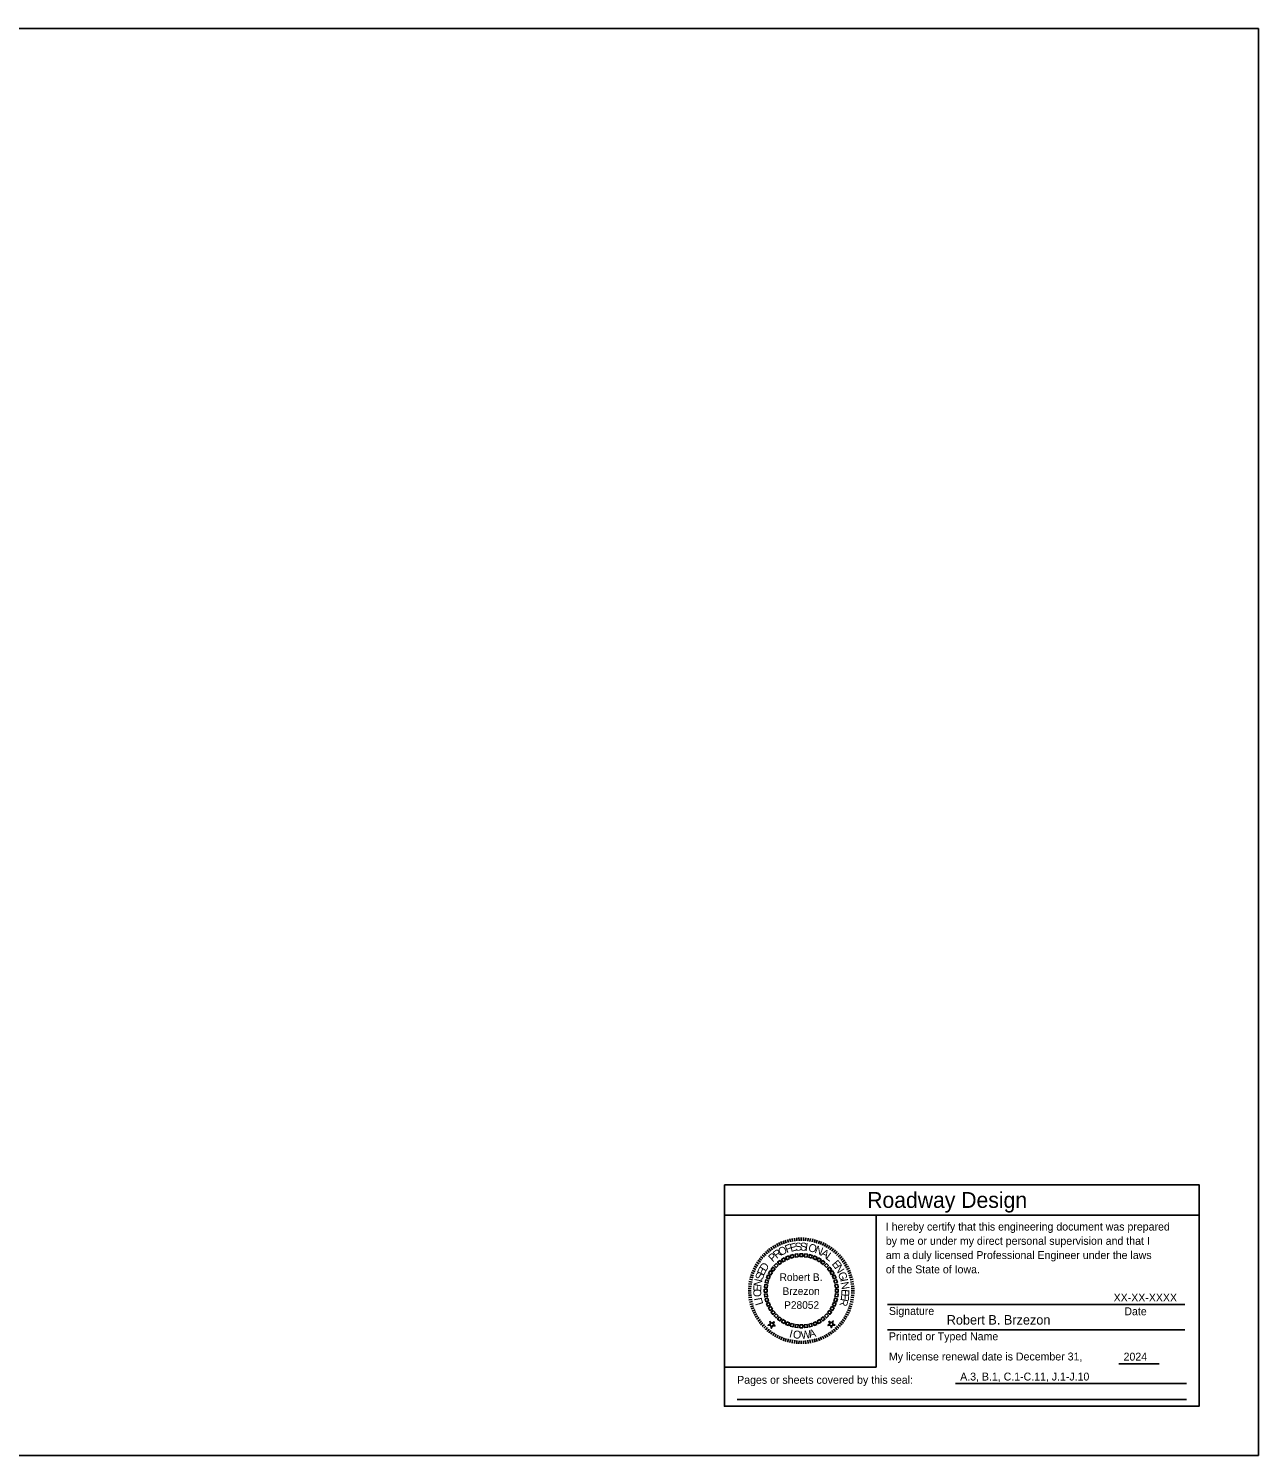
# Model space of a CAD drawing. Extents: x 10133 to 81668, y 7924 to 11018.
# Drawn here: x 11526 to 13268, y 7924 to 9944 of the extents above; entities that cross this region are included whole.
import ezdxf

# ---------------------------------------------------------------- set-up
doc = ezdxf.new("R2010")
doc.units = 0
for name, color, linetype in [('Level 1', 7, 'Continuous'), ('Level 20', 7, 'Continuous'), ('Level 21', 7, 'Continuous'), ('Level 22', 7, 'Continuous'), ('Level 4', 7, 'Continuous'), ('SheetBorder', 7, 'Continuous'), ('SheetText', 7, 'Continuous')]:
    doc.layers.add(name, color=color, linetype=linetype)

msp = doc.modelspace()

# ---------------------------------------------------------------- linework, layer by layer
at = {"layer": 'Level 20'}
msp.add_lwpolyline([(12511.5, 8307.2), (13183.4, 8307.2), (13183.4, 7993.7), (12511.5, 7993.7)], close=True, dxfattribs=at)
at = {"layer": 'Level 21'}
for p, q in [((12511.5, 8264.2), (13183.4, 8264.2)), ((12726.5, 8049.2), (12726.5, 8264.2)), ((12511.5, 8049.2), (12726.5, 8049.2))]:
    msp.add_line(p, q, dxfattribs=at)
msp.add_lwpolyline([(12511.5, 8307.2), (13183.4, 8307.2), (13183.4, 7993.7), (12511.5, 7993.7)], close=True, dxfattribs=at)
at = {"layer": 'Level 22'}
for p, q in [((13163.3, 8137.7), (12742.3, 8137.7)), ((13163.3, 8101.9), (12742.3, 8101.9)), ((13126.9, 8053.9), (13069.7, 8053.9)), ((12838.5, 8025.7), (13165.5, 8025.7)), ((12529.5, 8003.3), (13165.5, 8003.3))]:
    msp.add_line(p, q, dxfattribs=at)
at = {"layer": 'Level 4'}
for p, q in [((12584.9, 8218.5), (12582.7, 8222.4)), ((12587.7, 8220), (12585.6, 8224)), ((12590.4, 8221.3), (12588.5, 8225.4)), ((12593.2, 8222.6), (12591.5, 8226.7)), ((12596.1, 8223.7), (12594.6, 8227.9)), ((12599.1, 8224.7), (12597.7, 8229)), ((12602, 8225.6), (12600.9, 8229.9)), ((12605, 8226.3), (12604, 8230.7)), ((12608, 8226.9), (12607.3, 8231.3)), ((12611.1, 8227.4), (12610.5, 8231.8)), ((12614.2, 8227.7), (12613.8, 8232.2)), ((12617.2, 8227.9), (12617, 8232.4)), ((12620.3, 8228), (12620.3, 8232.5)), ((12623.4, 8227.9), (12623.6, 8232.4)), ((12626.5, 8227.7), (12626.9, 8232.2)), ((12629.6, 8227.4), (12630.2, 8231.8)), ((12632.6, 8226.9), (12633.4, 8231.3)), ((12635.6, 8226.3), (12636.6, 8230.7)), ((12638.6, 8225.6), (12639.8, 8229.9)), ((12641.6, 8224.7), (12643, 8229)), ((12644.5, 8223.7), (12646.1, 8227.9)), ((12647.4, 8222.6), (12649.1, 8226.7)), ((12650.2, 8221.3), (12652.1, 8225.4)), ((12653, 8220), (12655.1, 8224)), ((12655.7, 8218.5), (12658, 8222.4)), ((12564.2, 8200.3), (12560.6, 8203)), ((12566.1, 8202.7), (12562.7, 8205.6)), ((12568.2, 8205), (12564.9, 8208)), ((12570.3, 8207.3), (12567.1, 8210.4)), ((12572.5, 8209.4), (12569.5, 8212.7)), ((12574.8, 8211.4), (12572, 8214.9)), ((12577.2, 8213.4), (12574.5, 8216.9)), ((12579.7, 8215.2), (12577.2, 8218.9)), ((12582.3, 8216.9), (12579.9, 8220.7)), ((12658.4, 8216.9), (12660.8, 8220.7)), ((12660.9, 8215.2), (12663.5, 8218.8)), ((12663.4, 8213.4), (12666.1, 8216.9)), ((12665.8, 8211.4), (12668.7, 8214.9)), ((12668.1, 8209.4), (12671.2, 8212.7)), ((12670.4, 8207.3), (12673.5, 8210.4)), ((12672.5, 8205), (12675.8, 8208)), ((12674.5, 8202.7), (12678, 8205.6)), ((12676.5, 8200.3), (12680, 8203)), ((12553.8, 8181.4), (12549.6, 8182.9)), ((12554.9, 8184.3), (12550.8, 8186)), ((12556.2, 8187.1), (12552.1, 8189)), ((12557.6, 8189.9), (12553.6, 8192)), ((12559, 8192.6), (12555.2, 8194.8)), ((12560.6, 8195.2), (12556.9, 8197.6)), ((12562.4, 8197.8), (12558.7, 8200.4)), ((12678.3, 8197.8), (12682, 8200.4)), ((12680, 8195.2), (12683.8, 8197.6)), ((12681.6, 8192.6), (12685.5, 8194.8)), ((12683.1, 8189.9), (12687.1, 8192)), ((12684.5, 8187.1), (12688.5, 8189)), ((12685.7, 8184.3), (12689.9, 8186)), ((12686.8, 8181.4), (12691, 8182.9)), ((12549.8, 8163.4), (12545.4, 8163.8)), ((12550.2, 8166.4), (12545.7, 8167)), ((12550.6, 8169.5), (12546.2, 8170.3)), ((12551.2, 8172.5), (12546.9, 8173.5)), ((12552, 8175.5), (12547.6, 8176.7)), ((12552.8, 8178.5), (12548.6, 8179.8)), ((12687.8, 8178.5), (12692.1, 8179.8)), ((12688.7, 8175.5), (12693, 8176.7)), ((12689.4, 8172.5), (12693.8, 8173.5)), ((12690, 8169.5), (12694.4, 8170.3)), ((12690.5, 8166.4), (12694.9, 8167)), ((12690.8, 8163.4), (12695.3, 8163.8)), ((12549.6, 8157.2), (12545.1, 8157.2)), ((12549.6, 8160.3), (12545.2, 8160.5)), ((12549.6, 8154.1), (12545.2, 8153.9)), ((12549.8, 8151), (12545.4, 8150.7)), ((12550.2, 8148), (12545.7, 8147.4)), ((12550.6, 8144.9), (12546.2, 8144.1)), ((12551.2, 8141.9), (12546.9, 8140.9)), ((12689.4, 8141.9), (12693.8, 8140.9)), ((12690, 8144.9), (12694.4, 8144.1)), ((12690.5, 8148), (12694.9, 8147.4)), ((12690.8, 8151), (12695.3, 8150.6)), ((12691, 8160.3), (12695.5, 8160.5)), ((12691, 8154.1), (12695.5, 8153.9)), ((12691.1, 8157.2), (12695.6, 8157.2)), ((12552, 8138.9), (12547.6, 8137.7)), ((12552.8, 8135.9), (12548.6, 8134.6)), ((12553.8, 8133), (12549.6, 8131.5)), ((12554.9, 8130.1), (12550.8, 8128.4)), ((12556.2, 8127.3), (12552.1, 8125.4)), ((12557.6, 8124.5), (12553.6, 8122.5)), ((12559, 8121.8), (12555.2, 8119.6)), ((12681.6, 8121.8), (12685.5, 8119.6)), ((12683.1, 8124.5), (12687.1, 8122.5)), ((12684.5, 8127.3), (12688.5, 8125.4)), ((12685.7, 8130.1), (12689.9, 8128.4)), ((12686.8, 8133), (12691, 8131.5)), ((12687.8, 8135.9), (12692.1, 8134.6)), ((12688.7, 8138.9), (12693, 8137.7)), ((12560.6, 8119.2), (12556.9, 8116.8)), ((12562.4, 8116.6), (12558.7, 8114)), ((12564.2, 8114.1), (12560.6, 8111.4)), ((12566.1, 8111.7), (12562.7, 8108.8)), ((12568.2, 8109.4), (12564.8, 8106.4)), ((12570.3, 8107.2), (12567.1, 8104)), ((12572.5, 8105), (12569.5, 8101.7)), ((12574.8, 8103), (12572, 8099.6)), ((12577.2, 8101.1), (12574.5, 8097.5)), ((12663.4, 8101.1), (12666.1, 8097.5)), ((12665.8, 8103), (12668.7, 8099.6)), ((12668.1, 8105), (12671.2, 8101.7)), ((12670.4, 8107.2), (12673.5, 8104)), ((12672.5, 8109.4), (12675.8, 8106.4)), ((12674.5, 8111.7), (12678, 8108.8)), ((12676.5, 8114.1), (12680, 8111.4)), ((12678.3, 8116.6), (12682, 8114)), ((12680, 8119.2), (12683.8, 8116.8)), ((12579.7, 8099.2), (12577.2, 8095.6)), ((12582.3, 8097.5), (12579.9, 8093.7)), ((12584.9, 8095.9), (12582.7, 8092)), ((12587.7, 8094.4), (12585.6, 8090.5)), ((12590.4, 8093.1), (12588.5, 8089)), ((12593.2, 8091.8), (12591.5, 8087.7)), ((12596.1, 8090.7), (12594.6, 8086.5)), ((12599, 8089.7), (12597.7, 8085.4)), ((12602, 8088.9), (12600.9, 8084.5)), ((12605, 8088.1), (12604, 8083.7)), ((12608, 8087.5), (12607.3, 8083.1)), ((12611.1, 8087), (12610.5, 8082.6)), ((12614.2, 8086.7), (12613.8, 8082.2)), ((12617.2, 8086.5), (12617, 8082)), ((12620.3, 8086.4), (12620.3, 8082)), ((12623.4, 8086.5), (12623.6, 8082)), ((12626.5, 8086.7), (12626.9, 8082.2)), ((12629.6, 8087), (12630.2, 8082.6)), ((12632.6, 8087.5), (12633.4, 8083.1)), ((12635.6, 8088.1), (12636.6, 8083.7)), ((12638.6, 8088.9), (12639.8, 8084.5)), ((12641.6, 8089.7), (12643, 8085.4)), ((12644.5, 8090.7), (12646.1, 8086.5)), ((12647.4, 8091.8), (12649.1, 8087.7)), ((12650.2, 8093.1), (12652.1, 8089)), ((12653, 8094.4), (12655.1, 8090.5)), ((12655.7, 8095.9), (12658, 8092)), ((12658.4, 8097.5), (12660.8, 8093.7)), ((12660.9, 8099.2), (12663.5, 8095.6))]:
    msp.add_line(p, q, dxfattribs=at)
for points in [[(12597.9, 8200.1), (12594.4, 8198.1), (12592.4, 8201.6), (12595.9, 8203.6)], [(12603.7, 8202.7), (12600, 8201.1), (12598.4, 8204.9), (12602.1, 8206.4)], [(12609.8, 8204.5), (12605.9, 8203.4), (12604.8, 8207.3), (12608.7, 8208.4)], [(12616, 8205.4), (12612, 8204.9), (12611.5, 8208.9), (12615.5, 8209.4)], [(12622.3, 8205.6), (12618.3, 8205.6), (12618.3, 8209.6), (12622.3, 8209.6)], [(12628.6, 8204.9), (12624.6, 8205.4), (12625.2, 8209.4), (12629.2, 8208.9)], [(12634.8, 8203.4), (12630.9, 8204.5), (12631.9, 8208.4), (12635.8, 8207.3)], [(12640.7, 8201.1), (12637, 8202.7), (12638.5, 8206.4), (12642.2, 8204.9)], [(12646.3, 8198.1), (12642.8, 8200.1), (12644.8, 8203.6), (12648.3, 8201.6)], [(12579.4, 8183.1), (12577.4, 8179.6), (12573.9, 8181.7), (12576, 8185.2)], [(12583.2, 8188.3), (12580.7, 8185.1), (12577.5, 8187.5), (12580, 8190.7)], [(12587.5, 8192.8), (12584.7, 8190), (12581.8, 8192.8), (12584.7, 8195.7)], [(12592.5, 8196.8), (12589.3, 8194.4), (12586.8, 8197.6), (12590, 8200)], [(12651.4, 8194.4), (12648.2, 8196.8), (12650.6, 8200), (12653.8, 8197.6)], [(12656, 8190), (12653.1, 8192.8), (12656, 8195.7), (12658.8, 8192.8)], [(12659.9, 8185.1), (12657.5, 8188.3), (12660.7, 8190.7), (12663.1, 8187.5)], [(12663.2, 8179.7), (12661.2, 8183.1), (12664.7, 8185.2), (12666.7, 8181.7)], [(12572.6, 8165.5), (12572.1, 8161.5), (12568.1, 8162.1), (12568.6, 8166)], [(12574.1, 8171.7), (12573.1, 8167.8), (12569.2, 8168.8), (12570.2, 8172.7)], [(12576.4, 8177.6), (12574.9, 8173.9), (12571.1, 8175.4), (12572.7, 8179.1)], [(12665.8, 8173.9), (12664.3, 8177.6), (12668, 8179.1), (12669.5, 8175.4)], [(12667.6, 8167.8), (12666.5, 8171.7), (12670.4, 8172.7), (12671.5, 8168.8)], [(12668.6, 8161.5), (12668, 8165.5), (12672, 8166), (12672.6, 8162.1)], [(12572, 8159.2), (12572, 8155.2), (12567.9, 8155.2), (12567.9, 8159.2)], [(12572.1, 8152.9), (12572.6, 8148.9), (12568.6, 8148.4), (12568.1, 8152.4)], [(12573.1, 8146.6), (12574.1, 8142.7), (12570.2, 8141.7), (12569.2, 8145.6)], [(12666.5, 8142.7), (12667.6, 8146.6), (12671.5, 8145.6), (12670.4, 8141.7)], [(12668, 8148.9), (12668.6, 8152.9), (12672.6, 8152.4), (12672, 8148.4)], [(12668.7, 8155.2), (12668.7, 8159.2), (12672.7, 8159.2), (12672.7, 8155.2)], [(12574.9, 8140.6), (12576.4, 8136.8), (12572.7, 8135.3), (12571.1, 8139)], [(12577.4, 8134.8), (12579.4, 8131.3), (12576, 8129.3), (12573.9, 8132.8)], [(12580.7, 8129.4), (12583.2, 8126.2), (12580, 8123.7), (12577.5, 8126.9)], [(12584.7, 8124.4), (12587.5, 8121.6), (12584.7, 8118.7), (12581.8, 8121.6)], [(12653.1, 8121.6), (12656, 8124.4), (12658.8, 8121.6), (12656, 8118.7)], [(12657.5, 8126.2), (12659.9, 8129.4), (12663.1, 8126.9), (12660.7, 8123.7)], [(12661.2, 8131.3), (12663.2, 8134.8), (12666.7, 8132.8), (12664.7, 8129.3)], [(12664.3, 8136.8), (12665.8, 8140.6), (12669.5, 8139), (12668, 8135.3)], [(12575.8, 8114), (12578.6, 8111.4), (12581.9, 8113.3), (12580.4, 8109.8), (12583.2, 8107.3), (12579.4, 8107.7), (12577.9, 8104.2), (12577.1, 8107.9), (12573.3, 8108.3), (12576.6, 8110.2)], [(12589.3, 8120.1), (12592.5, 8117.6), (12590, 8114.4), (12586.8, 8116.9)], [(12594.4, 8116.3), (12597.9, 8114.3), (12595.9, 8110.8), (12592.4, 8112.8)], [(12600, 8113.3), (12603.7, 8111.7), (12602.1, 8108), (12598.4, 8109.6)], [(12605.9, 8111), (12609.8, 8110), (12608.7, 8106.1), (12604.8, 8107.1)], [(12612, 8109.5), (12616, 8109), (12615.5, 8105), (12611.5, 8105.5)], [(12618.3, 8108.8), (12622.3, 8108.8), (12622.3, 8104.8), (12618.3, 8104.8)], [(12624.6, 8109), (12628.6, 8109.5), (12629.2, 8105.5), (12625.2, 8105)], [(12630.9, 8110), (12634.8, 8111), (12635.8, 8107.1), (12631.9, 8106.1)], [(12637, 8111.7), (12640.7, 8113.3), (12642.2, 8109.6), (12638.5, 8108)], [(12642.8, 8114.3), (12646.3, 8116.3), (12648.3, 8112.8), (12644.8, 8110.8)], [(12648.2, 8117.6), (12651.4, 8120.1), (12653.8, 8116.9), (12650.6, 8114.4)], [(12659.5, 8114), (12662.7, 8112), (12665.6, 8114.4), (12664.7, 8110.7), (12667.9, 8108.7), (12664.1, 8108.4), (12663.2, 8104.7), (12661.8, 8108.3), (12658, 8108), (12660.9, 8110.4)]]:
    msp.add_lwpolyline(points, close=True, dxfattribs=at)
at = {"layer": 'SheetBorder'}
msp.add_lwpolyline([(10132.5, 9944), (13267.5, 9944), (13267.5, 7924), (10132.5, 7924)], close=True, dxfattribs=at)

# ---------------------------------------------------------------- texts
at = {"layer": 'Level 1'}
for s, p in [('Robert B.', (12589.6, 8171.1)), ('Brzezon', (12593.7, 8151.3)), ('P28052', (12596, 8131.6))]:
    msp.add_text(s, height=10.75, dxfattribs=at).set_placement(p)
at = {"layer": 'Level 4'}
for s, rotation, p in [('F', 21.7736, (12599.8, 8210.2)), ('E', 14.5823, (12605.7, 8212.1)), ('S', 7.3911, (12612, 8213.4)), ('S', 0.1998, (12618.5, 8214)), ('I', 353.0085, (12625.1, 8213.8)), ('O', 345.8172, (12629.4, 8213.5)), ('P', 43.3475, (12580, 8197.2)), ('R', 36.1562, (12585.4, 8202)), ('O', 28.9649, (12591.3, 8206)), ('N', 338.6259, (12638.5, 8211.1)), ('A', 331.4346, (12647.1, 8207.3)), ('L', 324.2434, (12654, 8203)), ('S', 72.1126, (12565.3, 8171.4)), ('E', 64.9213, (12567.2, 8177.7)), ('D', 57.7301, (12569.9, 8183.6)), ('E', 309.8608, (12662.9, 8194.8)), ('N', 302.6695, (12666.9, 8189.8)), ('G', 288.2869, (12672, 8181.8)), ('E', 86.4952, (12563.4, 8155.7)), ('N', 79.3039, (12563.5, 8162.2)), ('I', 281.0956, (12675.1, 8173)), ('N', 281.0956, (12675.9, 8168.8)), ('C', 93.6865, (12564, 8148.7)), ('I', 100.8778, (12565, 8144.5)), ('L', 108.069, (12566.7, 8138.7)), ('R', 259.086, (12676.2, 8146.9)), ('E', 266.2773, (12677, 8153.3)), ('E', 266.2773, (12677.4, 8159.7)), ('I', 345.2906, (12602.5, 8091.6)), ('O', 352.4819, (12608, 8090.3)), ('W', 6.8645, (12620.3, 8088.7)), ('A', 14.0557, (12632.3, 8090.1))]:
    msp.add_text(s, height=11.2, rotation=rotation, dxfattribs=at).set_placement(p)
at = {"layer": 'SheetText'}
for s, height, p in [('Roadway Design', 22.396, (12713.6, 8274.5)), ('I hereby certify that this engineering document was prepared', 11.198, (12740, 8242.4)), ('by me or under my direct personal supervision and that I', 11.198, (12740, 8222.2)), ('am a duly licensed Professional Engineer under the laws', 11.198, (12740, 8202.1)), ('of the State of Iowa.', 11.198, (12740, 8181.9)), ('XX-XX-XXXX', 11.18, (13062.5, 8142)), ('Signature', 11.2, (12744.4, 8123)), ('Robert B. Brzezon', 13.438, (12826.2, 8109.3)), ('Date', 11.2, (13077.7, 8122.5)), ('Printed or Typed Name', 11.198, (12744.4, 8087.1)), ('My license renewal date is December 31,', 11.198, (12744.4, 8058.5)), ('2024', 11.18, (13076.6, 8058.3)), ('A.3, B.1, C.1-C.11, J.1-J.10', 11.18, (12845.3, 8030.1)), ('Pages or sheets covered by this seal:', 11.198, (12529.5, 8025.5))]:
    msp.add_text(s, height=height, dxfattribs=at).set_placement(p)

doc.saveas('drawing.dxf')
